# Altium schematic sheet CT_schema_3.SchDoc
size 289 x 230 mm
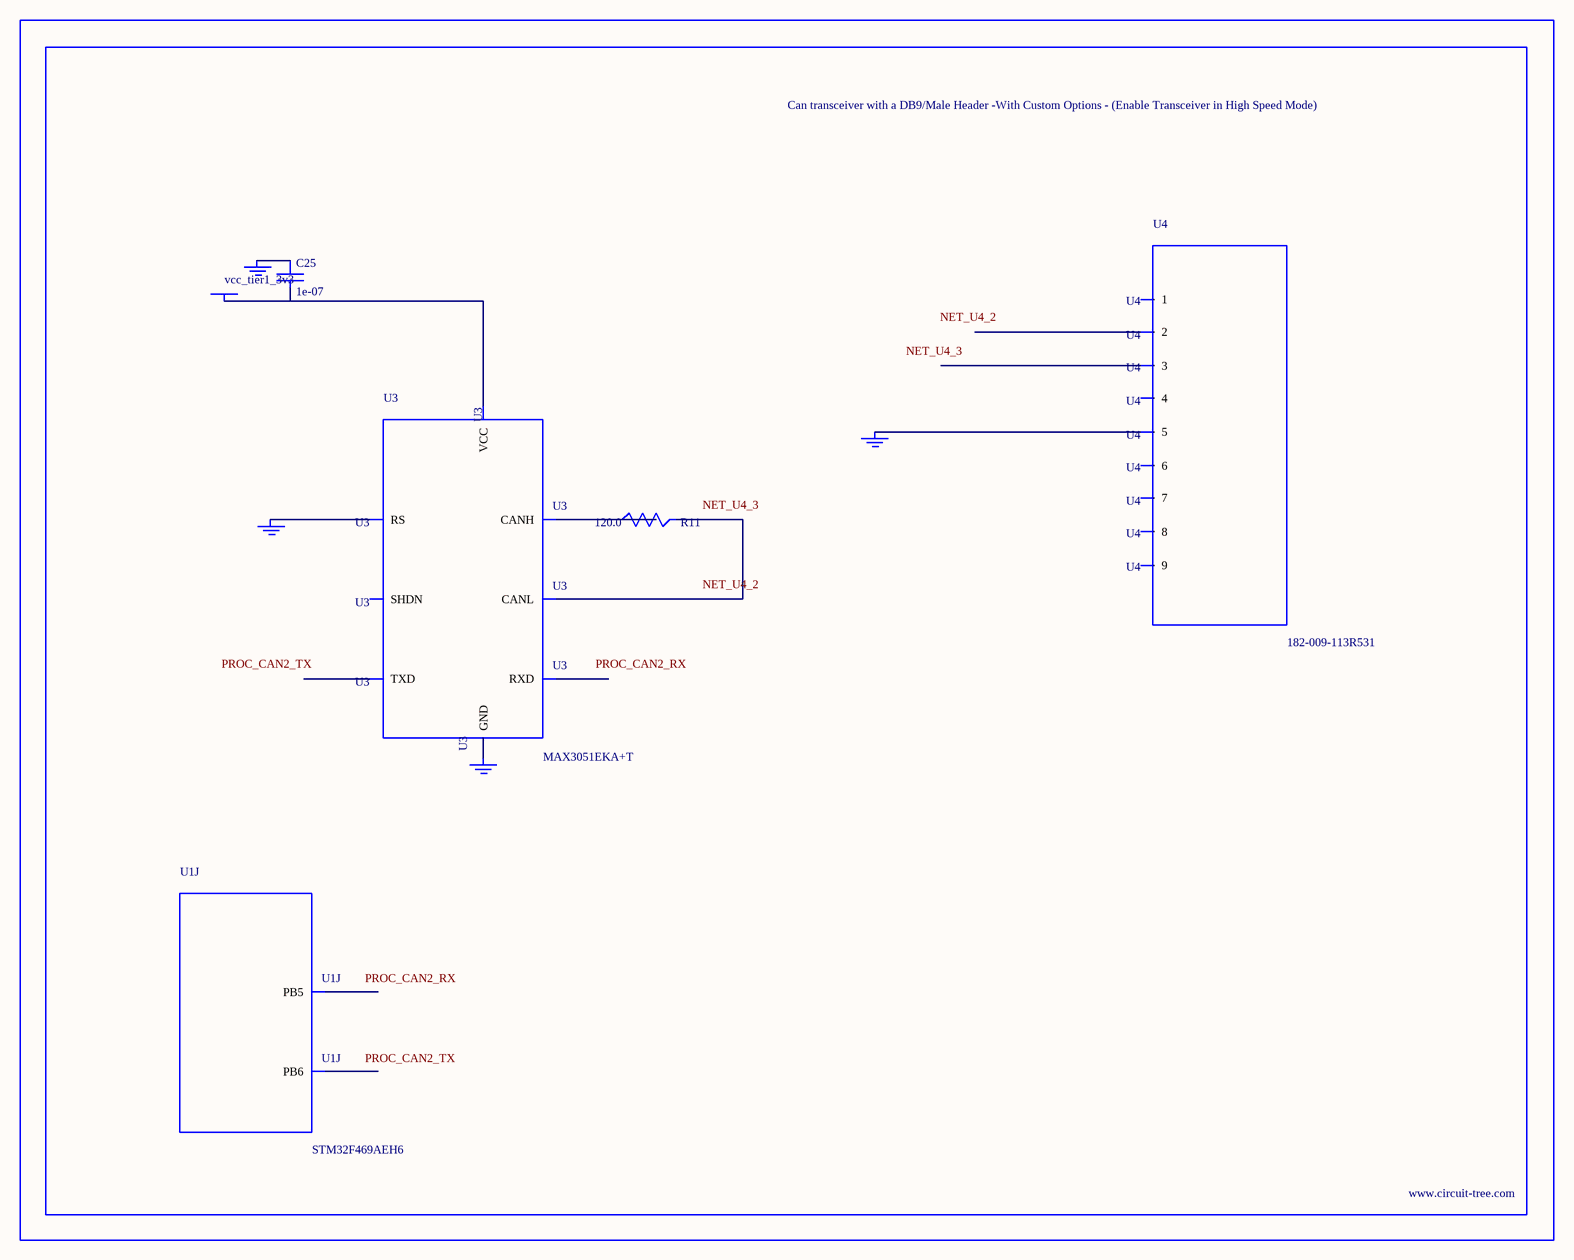
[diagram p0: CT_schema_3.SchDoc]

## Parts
BORDER2  (no value)
C25  1e-07  [C0402]
GND_INSTANCE_2_0  (no value)
GND_INSTANCE_2_1  (no value)
GND_INSTANCE_2_2  (no value)
GND_INSTANCE_2_3  (no value)
POWER_INSTANCE_2_0  vcc_tier1_3v3
R11  120.0  [R0603]
U1  STM32F469AEH6  [UFBGA169]  (part J of 14)
U3  MAX3051EKA+T  [SOT-23-8]
U4  182-009-113R531  [182-009-MALE]

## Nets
NetC25_1: C25.1 GND_INSTANCE_2_0.0(GND)
NetC25_2: C25.2 POWER_INSTANCE_2_0.0(PWR) U3.3(VCC)
NetGND_INSTANCE_2_1_0: GND_INSTANCE_2_1.0(GND) U3.8(RS)
NetGND_INSTANCE_2_2_0: GND_INSTANCE_2_2.0(GND) U3.2(GND)
NetGND_INSTANCE_2_3_0: GND_INSTANCE_2_3.0(GND) U4.5
NetR11_1: R11.1 U3.7(CANH)
NetR11_2: R11.2 U3.6(CANL)

Not connected (* = marked no-connect by the designer): U1 C5(PB6) D5(PB5); U3 1(TXD) 4(RXD) 5(SHDN); U4 1 2 3 4 6 7 8 9

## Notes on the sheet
- Labels drawn without touching a wire or pin: NET_U4_2, NET_U4_3, PROC_CAN2_RX, PROC_CAN2_TX

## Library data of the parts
BORDER2 = BORDER_PAGE2
C25 = C0402C104K3RACTU
GND_INSTANCE_2_0-GND_INSTANCE_2_3 = GND
POWER_INSTANCE_2_0 = PWR
R11 = RC0603JR-07120RL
